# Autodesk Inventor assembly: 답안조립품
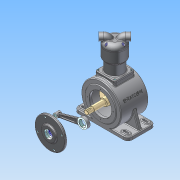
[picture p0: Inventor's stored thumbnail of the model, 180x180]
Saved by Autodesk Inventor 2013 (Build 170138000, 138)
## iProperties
Created: 2015-06
Part Number: 답안조립품
Document SubType Name: Assembly
Designer: Administrator
Author: Administrator
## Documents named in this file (9)
- C:\Users\Administrator\Desktop\450606V1014\답안조립품.iam
- C:\Users\Administrator\Desktop\450606V1014\본체.ipt
- C:\Users\Administrator\Desktop\450606V1014\메인 크랭크 축-구동부.ipt
- C:\Users\Administrator\Desktop\450606V1014\메인커버.ipt
- C:\Users\Administrator\Desktop\450606V1014\베어링 6204.ipt
- C:\Users\Administrator\Desktop\450606V1014\크랭크 서브축.ipt
- C:\Users\Administrator\Desktop\450606V1014\커넥팅 로드.ipt
- C:\Users\Administrator\Desktop\450606V1014\실린더.ipt
- C:\Users\Administrator\Desktop\450606V1014\실린더헤드.ipt
